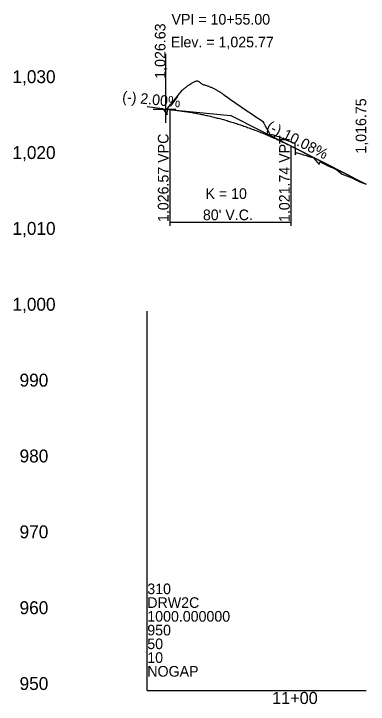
# Model space of a CAD drawing. Extents: x 1590191 to 1593577, y 1108634 to 1115609.
# Drawn here: x 1590190.9 to 1590424.8, y 1108634.4 to 1109089.4 of the extents above; entities that cross this region are included whole.
import ezdxf

# ---------------------------------------------------------------- set-up
doc = ezdxf.new("R2010")
doc.units = 0
for name, color, linetype in [('BR_USER NOTES', 7, 'Continuous'), ('RD_DDB_ElevTX', 7, 'Continuous'), ('RD_DDB_GradeTX', 7, 'Continuous'), ('RD_DDB_Profile_EX', 7, 'Continuous'), ('RD_DDB_Profile_Lbl', 7, 'Continuous'), ('RD_DDB_Profile_PR', 7, 'Continuous'), ('RD_DDB_StaTX', 7, 'Continuous'), ('RD_DDB_StripGrade', 7, 'Continuous'), ('RD_DDB_VCLbl', 7, 'Continuous'), ('RD_GPK_Profile_Cell', 7, 'Continuous')]:
    doc.layers.add(name, color=color, linetype=linetype)

msp = doc.modelspace()

# ---------------------------------------------------------------- linework, layer by layer
at = {"layer": 'BR_USER NOTES'}
for p, q in [((1590291.01, 1109063.04), (1590291.01, 1109017.56)), ((1590282.99, 1109026.62), (1590297.89, 1109026.62))]:
    msp.add_line(p, q, dxfattribs=at)
at = {"layer": 'RD_DDB_GradeTX'}
for p in [(1590291.01, 1109026.62), (1590412.6, 1108982.72)]:
    msp.add_line(p, (1590334.01, 1109022.32), dxfattribs=at)
at = {"layer": 'RD_DDB_Profile_EX'}
msp.add_lwpolyline([(1590279.01, 1109028.42), (1590279.11, 1109028.41), (1590287.26, 1109027.27), (1590289.14, 1109027.08), (1590290.05, 1109025.96), (1590290.43, 1109025.36), (1590291.74, 1109023.4), (1590292.07, 1109022.78), (1590292.36, 1109027.04), (1590293.08, 1109027.94), (1590293.52, 1109028.49), (1590293.97, 1109029.05), (1590294.41, 1109029.61), (1590294.86, 1109030.17), (1590295.3, 1109030.73), (1590295.75, 1109031.29), (1590296.19, 1109031.85), (1590296.64, 1109032.41), (1590297.08, 1109032.98), (1590297.52, 1109033.54), (1590297.97, 1109034.09), (1590298.41, 1109034.65), (1590298.86, 1109035.21), (1590299.3, 1109035.77), (1590299.75, 1109036.32), (1590300.19, 1109036.88), (1590300.64, 1109037.43), (1590301.08, 1109037.98), (1590301.53, 1109038.53), (1590301.97, 1109039.03), (1590302.42, 1109039.4), (1590302.86, 1109039.76), (1590303.31, 1109040.12), (1590303.75, 1109040.48), (1590304.2, 1109040.83), (1590304.64, 1109041.17), (1590305.09, 1109041.51), (1590305.53, 1109041.85), (1590305.98, 1109042.17), (1590306.42, 1109042.5), (1590306.87, 1109042.81), (1590307.31, 1109043.12), (1590307.89, 1109043.52), (1590308.2, 1109043.68), (1590308.65, 1109043.91), (1590309.09, 1109044.12), (1590309.53, 1109044.33), (1590309.98, 1109044.54), (1590310.42, 1109044.73), (1590310.87, 1109044.92), (1590311.31, 1109045.1), (1590311.76, 1109045.27), (1590312.2, 1109045.34), (1590312.65, 1109045.05), (1590313.09, 1109044.75), (1590313.54, 1109044.44), (1590313.98, 1109044.13), (1590314.43, 1109043.8), (1590314.87, 1109043.46), (1590315.32, 1109043.11), (1590315.71, 1109042.8), (1590316.21, 1109042.68), (1590316.65, 1109042.56), (1590317.1, 1109042.44), (1590317.54, 1109042.31), (1590317.99, 1109042.17), (1590318.43, 1109042.02), (1590318.88, 1109041.87), (1590319.32, 1109041.71), (1590319.77, 1109041.54), (1590320.21, 1109041.37), (1590320.65, 1109041.18), (1590321.1, 1109040.99), (1590321.54, 1109040.8), (1590321.99, 1109040.59), (1590322.43, 1109040.38), (1590323.32, 1109039.94), (1590323.77, 1109039.71), (1590324.21, 1109039.47), (1590324.66, 1109039.22), (1590325.1, 1109038.97), (1590325.55, 1109038.71), (1590325.99, 1109038.44), (1590326.44, 1109038.17), (1590326.88, 1109037.89), (1590327.33, 1109037.61), (1590327.77, 1109037.32), (1590328.22, 1109037.02), (1590328.66, 1109036.72), (1590329.11, 1109036.41), (1590329.55, 1109036.1), (1590331.3, 1109034.86), (1590333.05, 1109033.62), (1590334.8, 1109032.39), (1590336.55, 1109031.17), (1590338.31, 1109029.95), (1590340.06, 1109028.74), (1590341.81, 1109027.53), (1590343.56, 1109026.32), (1590345.31, 1109025.13), (1590346.19, 1109024.53), (1590347.06, 1109023.94), (1590348.81, 1109022.77), (1590350.56, 1109021.6), (1590352.31, 1109020.44), (1590354.06, 1109019.29), (1590355.27, 1109018.5), (1590355.81, 1109017.37), (1590356.69, 1109015.55), (1590357.56, 1109013.99), (1590359.32, 1109010.87), (1590359.99, 1109009.67), (1590361.07, 1109009.8), (1590361.47, 1109009.85), (1590362.82, 1109009.42), (1590364.57, 1109008.87), (1590365.65, 1109008.53), (1590366.32, 1109008.23), (1590368.07, 1109007.45), (1590369.82, 1109006.67), (1590371.57, 1109005.89), (1590372.1, 1109005.65), (1590373.32, 1109005.24), (1590375.07, 1109004.65), (1590376.41, 1109004.2), (1590376.5, 1108996.58), (1590376.82, 1108997.01), (1590377.51, 1108997.93), (1590378.57, 1108997.6), (1590380.33, 1108997.05), (1590382.08, 1108996.52), (1590383.83, 1108996), (1590385.58, 1108995.48), (1590387.33, 1108994.98), (1590387.77, 1108994.86), (1590388.65, 1108994.5), (1590389.09, 1108993.98), (1590389.52, 1108993.46), (1590389.96, 1108992.95), (1590390.4, 1108992.44), (1590390.84, 1108991.95), (1590391.28, 1108991.46), (1590391.72, 1108990.97), (1590392.16, 1108990.5), (1590392.48, 1108990.16), (1590392.85, 1108991.96), (1590393.48, 1108991.63), (1590393.92, 1108991.41), (1590394.36, 1108991.18), (1590394.8, 1108990.94), (1590395.24, 1108990.71), (1590395.67, 1108990.48), (1590396.11, 1108990.25), (1590396.55, 1108990.01), (1590396.99, 1108989.78), (1590397.43, 1108989.55), (1590397.87, 1108989.37), (1590398.31, 1108989.19), (1590398.75, 1108989.01), (1590399.19, 1108988.83), (1590399.63, 1108988.64), (1590400.07, 1108988.45), (1590400.51, 1108988.26), (1590400.95, 1108988.07), (1590401.39, 1108987.88), (1590401.82, 1108987.68), (1590402.26, 1108987.49), (1590402.7, 1108987.29), (1590403.58, 1108986.84), (1590404.02, 1108986.51), (1590407.66, 1108983.75), (1590413.94, 1108981.25), (1590419.17, 1108978.7), (1590423.48, 1108977.24)], dxfattribs=at)
at = {"layer": 'RD_DDB_Profile_PR'}
for p, q in [((1590291.01, 1109026.62), (1590294.01, 1109026.32)), ((1590374.01, 1109002.17), (1590423.48, 1108977.24))]:
    msp.add_line(p, q, dxfattribs=at)
msp.add_spline([(1590294.01, 1109026.32), (1590295.61, 1109026.16), (1590297.21, 1109025.98), (1590298.81, 1109025.79), (1590300.41, 1109025.58), (1590302.01, 1109025.36), (1590303.61, 1109025.13), (1590305.21, 1109024.89), (1590306.81, 1109024.63), (1590308.41, 1109024.36), (1590310.01, 1109024.08), (1590311.61, 1109023.78), (1590313.21, 1109023.47), (1590314.81, 1109023.15), (1590316.41, 1109022.82), (1590318.01, 1109022.47), (1590319.61, 1109022.11), (1590321.21, 1109021.74), (1590322.81, 1109021.35), (1590324.41, 1109020.95), (1590326.01, 1109020.54), (1590327.61, 1109020.11), (1590329.21, 1109019.68), (1590330.81, 1109019.23), (1590332.41, 1109018.76), (1590334.01, 1109018.29), (1590335.61, 1109017.8), (1590337.21, 1109017.29), (1590338.81, 1109016.78), (1590340.41, 1109016.25), (1590342.01, 1109015.71), (1590343.61, 1109015.15), (1590345.21, 1109014.59), (1590346.81, 1109014.01), (1590348.41, 1109013.41), (1590350.01, 1109012.81), (1590351.61, 1109012.19), (1590353.21, 1109011.56), (1590354.81, 1109010.91), (1590356.41, 1109010.26), (1590358.01, 1109009.58), (1590359.61, 1109008.9), (1590361.21, 1109008.2), (1590362.81, 1109007.5), (1590364.41, 1109006.77), (1590366.01, 1109006.04), (1590367.61, 1109005.29), (1590369.21, 1109004.53), (1590370.81, 1109003.75), (1590372.41, 1109002.97), (1590374.01, 1109002.17)], degree=3, dxfattribs=at)
at = {"layer": 'RD_DDB_VCLbl'}
for p, q in [((1590294.01, 1108949.67), (1590294.01, 1109026.32)), ((1590374.01, 1108949.67), (1590374.01, 1109002.17)), ((1590294.01, 1108952.17), (1590374.01, 1108952.17))]:
    msp.add_line(p, q, dxfattribs=at)
at = {"layer": 'RD_GPK_Profile_Cell'}
for q in [(1590279.01, 1108893.47), (1590423.48, 1108643.47), (1590279.01, 1108643.47)]:
    msp.add_line((1590279.01, 1108643.47), q, dxfattribs=at)

# ---------------------------------------------------------------- texts
at = {"layer": 'RD_DDB_ElevTX'}
for s, p in [('1,030', (1590190.05, 1109043.72)), ('1,020', (1590190.05, 1108993.72)), ('1,010', (1590190.05, 1108943.72)), ('1,000', (1590190.05, 1108893.72)), ('990', (1590194.73, 1108843.72)), ('980', (1590194.73, 1108793.72)), ('970', (1590194.73, 1108743.72)), ('960', (1590194.73, 1108693.72)), ('950', (1590194.73, 1108643.72))]:
    msp.add_text(s, height=8.5, dxfattribs=at).set_placement(p)
at = {"layer": 'RD_DDB_GradeTX'}
for s, rotation, p in [('(-) 2.00%', 354.2894, (1590262.25, 1109031.51)), ('(-) 10.08%', 333.2561, (1590357.01, 1109012.98))]:
    msp.add_text(s, height=7, rotation=rotation, dxfattribs=at).set_placement(p)
at = {"layer": 'RD_DDB_Profile_Lbl'}
for s, p in [('VPI = 10+55.00', (1590294.99, 1109082.32)), ('Elev. = 1,025.77', (1590294.55, 1109067.32))]:
    msp.add_text(s, height=7, dxfattribs=at).set_placement(p)
for s, p in [('1,026.63', (1590291.01, 1109046.62)), ('1,016.75', (1590423.48, 1108997.24))]:
    msp.add_text(s, height=7, rotation=90, dxfattribs=at).set_placement(p)
at = {"layer": 'RD_DDB_StaTX'}
msp.add_text('11+00', height=8, dxfattribs=at).set_placement((1590361.42, 1108634.47))
at = {"layer": 'RD_DDB_StripGrade'}
for s, p in [('1,026.57 VPC', (1590293.01, 1108952.17)), ('1,021.74 VPT', (1590373.01, 1108952.17))]:
    msp.add_text(s, height=7, rotation=90, dxfattribs=at).set_placement(p)
at = {"layer": 'RD_DDB_VCLbl'}
for s, p in [('K = 10', (1590317.39, 1108967.42)), ("80' V.C.", (1590315.7, 1108953.42))]:
    msp.add_text(s, height=7, dxfattribs=at).set_placement(p)
at = {"layer": 'RD_GPK_Profile_Cell'}
for s, p in [('310', (1590279.01, 1108706.89)), ('DRW2C', (1590279.01, 1108697.83)), ('1000.000000', (1590279.01, 1108688.77)), ('950', (1590279.01, 1108679.71)), ('50', (1590279.01, 1108670.65)), ('10', (1590279.01, 1108661.59)), ('NOGAP', (1590279.01, 1108652.53))]:
    msp.add_text(s, height=7, dxfattribs=at).set_placement(p)

doc.saveas('drawing.dxf')
